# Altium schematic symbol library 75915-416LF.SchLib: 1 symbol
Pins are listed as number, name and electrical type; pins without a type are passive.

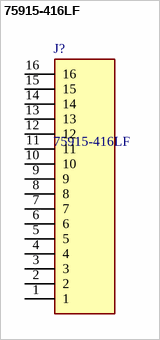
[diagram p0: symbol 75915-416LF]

## 75915-416LF
designator J?
Dubox, Board To Board Connector, Receptacle, Vertical, Through Hole, Single Row, Top Entry, 16 Positions, 2.54mm (0.100in) Pitch; Manufacturer_Name: Amphenol; Geometry.Height: 8.8mm
footprint 75915416LF
pins: 1, 2, 3, 4, 5, 6, 7, 8, 9, 10, 11, 12, 13, 14, 15, 16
